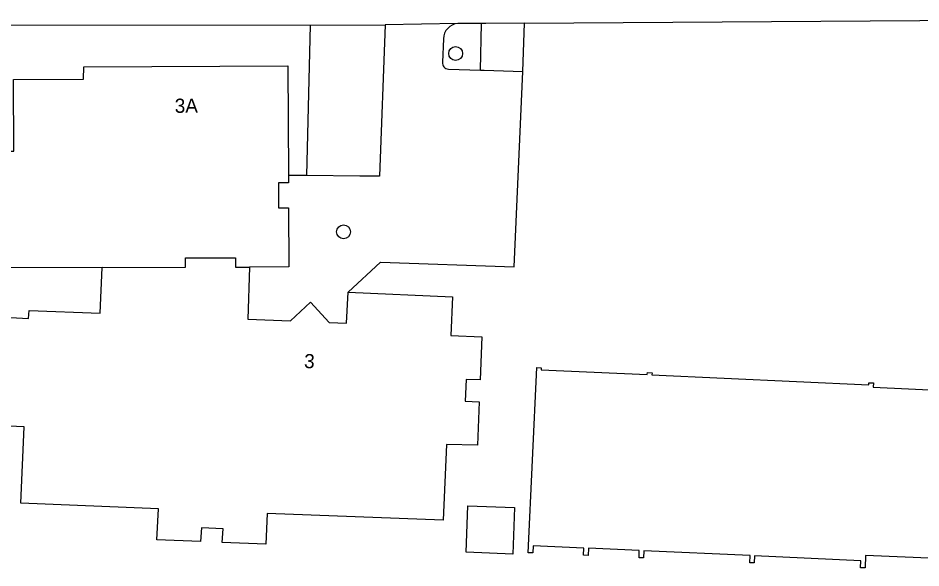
# Model space of a CAD drawing. Extents: x 160732 to 162105, y 387428 to 388479.
# Drawn here: x 161189.6 to 161253.3, y 387766.2 to 387805 of the extents above; entities that cross this region are included whole.
import ezdxf

# ---------------------------------------------------------------- set-up
doc = ezdxf.new("R2010")
doc.units = 0
for name, color, linetype in [('IMGEO_Boom', 7, 'Continuous'), ('IMGEO_Pand', 7, 'Continuous'), ('IMGEO_Pand_nummerreeks', 7, 'Continuous'), ('IMGEO_Parkeervlak_open', 7, 'Continuous'), ('IMGEO_Rijbaan_lokaal_open', 7, 'Continuous'), ('IMGEO_Voetpad_open', 7, 'Continuous')]:
    doc.layers.add(name, color=color, linetype=linetype)

msp = doc.modelspace()

# ---------------------------------------------------------------- linework, layer by layer
at = {"layer": 'IMGEO_Boom'}
for centre in [(161220.48, 387802.484), (161212.571, 387789.889)]:
    msp.add_circle(centre, 0.489, dxfattribs=at)
at = {"layer": 'IMGEO_Pand'}
for points in [[(161195.528, 387787.365), (161188.653, 387787.339), (161188.624, 387795.584), (161189.283, 387795.589), (161189.28, 387800.643), (161194.221, 387800.675), (161194.239, 387801.54), (161208.642, 387801.619), (161208.672, 387793.863)], [(161208.672, 387793.863), (161208.674, 387793.357), (161207.973, 387793.354), (161207.979, 387791.591), (161208.679, 387791.593), (161208.694, 387787.417), (161205.919, 387787.406)], [(161195.528, 387787.365), (161201.422, 387787.387), (161201.42, 387788.048), (161204.935, 387788.062), (161204.938, 387787.402), (161205.919, 387787.406)], [(161188.152, 387783.879), (161190.319, 387783.762), (161190.374, 387784.335), (161195.398, 387784.136), (161195.528, 387787.365)], [(161205.919, 387787.406), (161205.814, 387783.722), (161208.825, 387783.603), (161210.238, 387784.915), (161211.556, 387783.477), (161212.787, 387783.447), (161212.894, 387785.627)], [(161212.894, 387785.627), (161220.265, 387785.309), (161220.151, 387782.573), (161222.341, 387782.482), (161222.214, 387779.427), (161221.219, 387779.468), (161221.156, 387777.926), (161222.152, 387777.886), (161222.025, 387774.83), (161219.832, 387774.879), (161219.602, 387769.524), (161207.181, 387769.993), (161207.08, 387767.819), (161203.997, 387767.949), (161204.061, 387768.923), (161202.543, 387768.988), (161202.46, 387768.011), (161199.395, 387768.137), (161199.496, 387770.321), (161189.791, 387770.727), (161190.02, 387776.114), (161187.825, 387776.207)], [(161254.442, 387766.811), (161249.423, 387767.04), (161249.382, 387766.15), (161249.062, 387766.163), (161249.084, 387766.663), (161241.587, 387767.005), (161241.563, 387766.505), (161241.243, 387766.519), (161241.265, 387767.018), (161233.768, 387767.361), (161233.745, 387766.861), (161233.425, 387766.875), (161233.447, 387767.374), (161229.858, 387767.538), (161229.835, 387767.037), (161229.515, 387767.051), (161229.537, 387767.55), (161225.948, 387767.714), (161225.925, 387767.214), (161225.604, 387767.227), (161226.202, 387780.311), (161226.521, 387780.297), (161226.514, 387780.147), (161234.01, 387779.803), (161234.016, 387779.952), (161234.345, 387779.936), (161234.338, 387779.786), (161249.652, 387779.085), (161249.658, 387779.234)], [(161249.658, 387779.234), (161249.967, 387779.22), (161249.953, 387778.91), (161254.95, 387778.68)], [(161224.643, 387770.418), (161224.516, 387767.114), (161221.228, 387767.275), (161221.339, 387770.545), (161224.643, 387770.418)]]:
    msp.add_lwpolyline(points, dxfattribs=at)
at = {"layer": 'IMGEO_Parkeervlak_open'}
msp.add_lwpolyline([(161209.983, 387793.86), (161210.227, 387804.485)], dxfattribs=at)
at = {"layer": 'IMGEO_Rijbaan_lokaal_open'}
for points in [[(161215.499, 387804.51), (161215.096, 387793.819), (161213.715, 387793.83), (161209.983, 387793.86)], [(161220.629, 387804.612), (161215.499, 387804.51)], [(161219.613, 387803.532), (161219.548, 387801.868)], [(161212.894, 387785.627), (161215.176, 387787.756), (161224.621, 387787.42), (161225.233, 387801.228)], [(161219.97, 387801.39), (161222.224, 387801.32)], [(161222.224, 387801.32), (161222.506, 387801.311), (161225.233, 387801.228)], [(161209.983, 387793.86), (161208.672, 387793.863)]]:
    msp.add_lwpolyline(points, dxfattribs=at)
for centre, radius, start, end in [((161220.742, 387803.488), 1.13, 95.73266, 177.76523), ((161219.978, 387801.822), 0.432, 173.94474, 268.93429)]:
    msp.add_arc(centre, radius, start, end, dxfattribs=at)
at = {"layer": 'IMGEO_Voetpad_open'}
for points in [[(161166.859, 387804.507), (161210.227, 387804.485)], [(161210.227, 387804.485), (161215.499, 387804.51)], [(161222.311, 387804.607), (161220.629, 387804.612)], [(161222.224, 387801.32), (161222.311, 387804.607)], [(161225.336, 387804.636), (161222.607, 387804.606), (161222.311, 387804.607)], [(161225.233, 387801.228), (161225.336, 387804.636)], [(161225.336, 387804.636), (161260.216, 387804.873), (161282.806, 387804.942), (161291.009, 387804.992)]]:
    msp.add_lwpolyline(points, dxfattribs=at)

# ---------------------------------------------------------------- texts
at = {"layer": 'IMGEO_Pand_nummerreeks'}
for s, rotation, p in [('3A', 0.31426, (161200.654, 387798.295)), ('3', 357.35842, (161209.765, 387780.276))]:
    msp.add_text(s, height=1, rotation=rotation, dxfattribs=at).set_placement(p)

doc.saveas('drawing.dxf')
